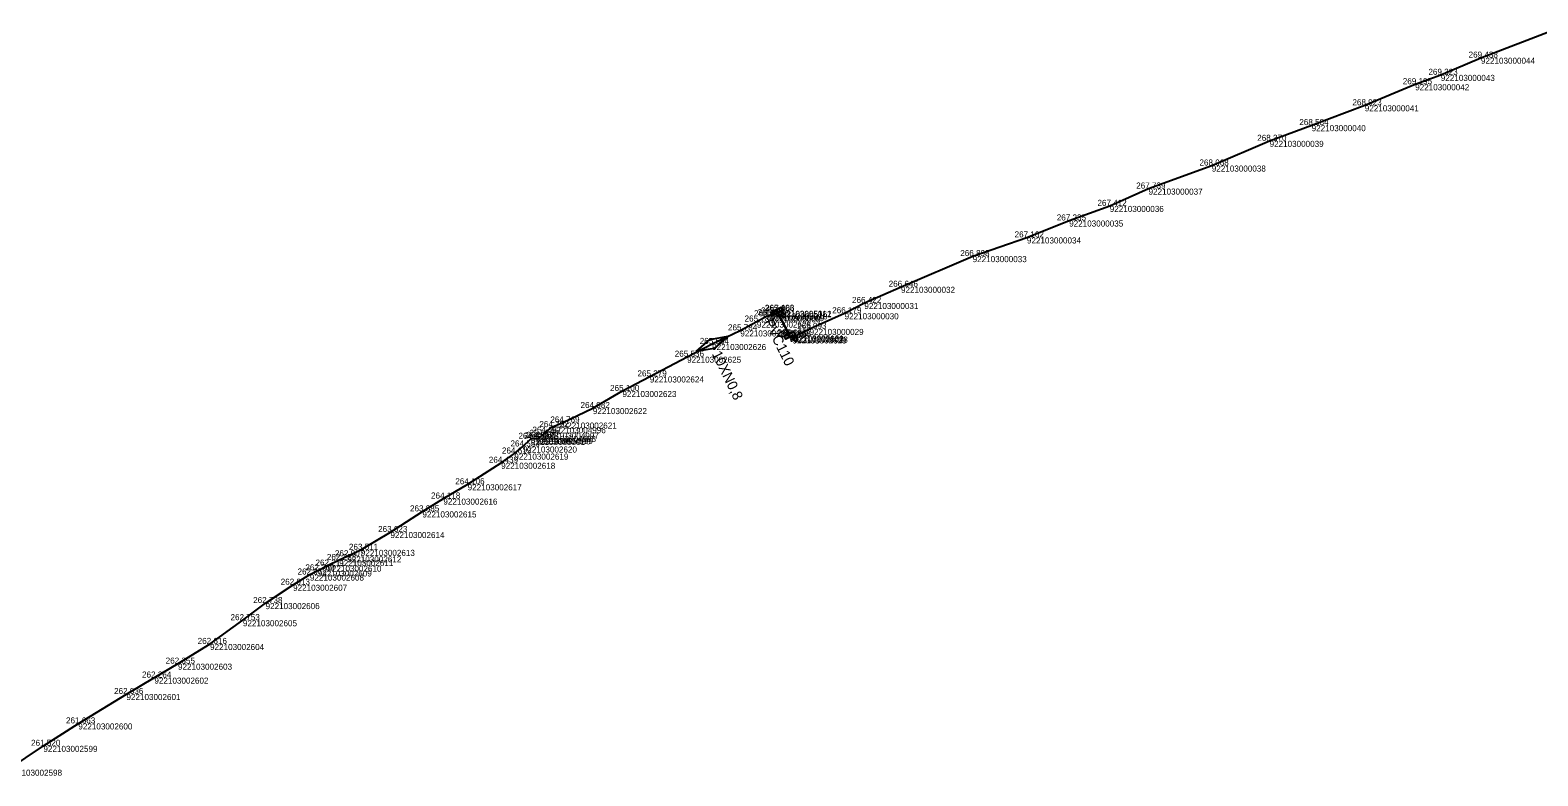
# Model space of a CAD drawing. Extents: x -771047 to -756200, y -1053876 to -1046520.
# Drawn here: x -762224.4 to -761925.6, y -1050432.5 to -1050284.9 of the extents above; entities that cross this region are included whole.
import ezdxf

# ---------------------------------------------------------------- set-up
doc = ezdxf.new("R2010")
doc.units = 0
for name, color, linetype in [('Vrstva 32', 7, 'Continuous'), ('Vrstva 33', 7, 'Continuous'), ('Vrstva 60', 7, 'Continuous'), ('Vrstva 61', 7, 'Continuous')]:
    doc.layers.add(name, color=color, linetype=linetype)

msp = doc.modelspace()

# ---------------------------------------------------------------- linework, layer by layer
at = {"layer": 'Vrstva 32'}
for points in [[(-762228.75, -1050431.27), (-762221.73, -1050426.55), (-762214.81, -1050422.11), (-762205.28, -1050416.29), (-762199.74, -1050413.04), (-762195.06, -1050410.28), (-762188.71, -1050406.38), (-762182.2, -1050401.68), (-762177.71, -1050398.29), (-762172.26, -1050394.66), (-762168.93, -1050392.64), (-762167.37, -1050391.82), (-762165.46, -1050390.88), (-762163.11, -1050389.76), (-762161.53, -1050389.03), (-762158.84, -1050387.75), (-762152.97, -1050384.22), (-762146.64, -1050380.14), (-762142.48, -1050377.6), (-762137.67, -1050374.77), (-762131.03, -1050370.51), (-762128.42, -1050368.69), (-762126.73, -1050367.29), (-762125.16, -1050365.77), (-762124.01, -1050365.69), (-762123.58, -1050365.58), (-762122.96, -1050365.19), (-762122.39, -1050364.57), (-762121.02, -1050363.46), (-762118.84, -1050362.55), (-762112.86, -1050359.68), (-762107.01, -1050356.3), (-762101.58, -1050353.42), (-762094.19, -1050349.51), (-762089.24, -1050346.99), (-762083.65, -1050344.31), (-762080.36, -1050342.56), (-762078.48, -1050341.51), (-762077.75, -1050341.27), (-762077.09, -1050340.94), (-762076.32, -1050340.42), (-762073.88, -1050345.37), (-762073.3, -1050345.7), (-762073.06, -1050345.53), (-762069.93, -1050344.01), (-762062.99, -1050340.91), (-762059.07, -1050338.88), (-762051.81, -1050335.67), (-762037.61, -1050329.6), (-762026.86, -1050325.9), (-762018.49, -1050322.55), (-762010.45, -1050319.66), (-762002.76, -1050316.23), (-761990.23, -1050311.67), (-761978.78, -1050306.78), (-761970.44, -1050303.67), (-761959.92, -1050299.74), (-761949.93, -1050295.57), (-761944.86, -1050293.72), (-761936.9, -1050290.32), (-761922.65, -1050284.88)], [(-762092.4, -1050348.51), (-762089.68, -1050346.09), (-762086.09, -1050345.48), (-762088.81, -1050347.9), (-762092.4, -1050348.51)]]:
    msp.add_lwpolyline(points, dxfattribs=at)
at = {"layer": 'Vrstva 33'}
for points in [[(-762075.53, -1050339.71), (-762075.21, -1050340.37), (-762077.01, -1050341.27), (-762077.34, -1050340.6)], [(-762073.14, -1050344.5), (-762072.81, -1050345.17), (-762074.61, -1050346.06), (-762074.94, -1050345.39)]]:
    msp.add_lwpolyline(points, close=True, dxfattribs=at)
for points in [[(-762073.88, -1050345.37), (-762076.32, -1050340.42)], [(-762076.09, -1050341.4), (-762074.97, -1050340.84)], [(-762075.29, -1050341.58), (-762075.52, -1050341.12)], [(-762074.74, -1050341.31), (-762074.72, -1050341.47), (-762074.85, -1050341.66), (-762074.95, -1050341.71), (-762075.18, -1050341.7), (-762075.29, -1050341.58)], [(-762074.97, -1050340.84), (-762074.74, -1050341.31)], [(-762073.7, -1050346.19), (-762072.57, -1050345.63)], [(-762072.9, -1050346.37), (-762073.13, -1050345.91)], [(-762072.34, -1050346.1), (-762072.32, -1050346.26), (-762072.45, -1050346.45), (-762072.55, -1050346.5), (-762072.79, -1050346.5), (-762072.9, -1050346.37)], [(-762072.57, -1050345.63), (-762072.34, -1050346.1)]]:
    msp.add_lwpolyline(points, dxfattribs=at)
at = {"layer": 'Vrstva 60'}
for p, q in [((-761936.9, -1050290.32), (-761936.9, -1050290.32)), ((-761944.86, -1050293.72), (-761944.86, -1050293.72)), ((-761949.93, -1050295.57), (-761949.93, -1050295.57)), ((-761959.92, -1050299.74), (-761959.92, -1050299.74)), ((-761970.44, -1050303.67), (-761970.44, -1050303.67)), ((-761978.78, -1050306.78), (-761978.78, -1050306.78)), ((-761990.23, -1050311.67), (-761990.23, -1050311.67)), ((-762002.76, -1050316.23), (-762002.76, -1050316.23)), ((-762010.45, -1050319.66), (-762010.45, -1050319.66)), ((-762018.49, -1050322.55), (-762018.49, -1050322.55)), ((-762026.86, -1050325.9), (-762026.86, -1050325.9)), ((-762037.61, -1050329.6), (-762037.61, -1050329.6)), ((-762051.81, -1050335.67), (-762051.81, -1050335.67)), ((-762059.07, -1050338.88), (-762059.07, -1050338.88)), ((-762078.48, -1050341.51), (-762078.48, -1050341.51)), ((-762077.75, -1050341.27), (-762077.75, -1050341.27)), ((-762077.09, -1050340.94), (-762077.09, -1050340.94)), ((-762076.32, -1050340.42), (-762076.32, -1050340.42)), ((-762076.27, -1050340.49), (-762076.27, -1050340.49)), ((-762062.99, -1050340.91), (-762062.99, -1050340.91)), ((-762083.65, -1050344.31), (-762083.65, -1050344.31)), ((-762080.36, -1050342.56), (-762080.36, -1050342.56)), ((-762069.93, -1050344.01), (-762069.93, -1050344.01)), ((-762089.24, -1050346.99), (-762089.24, -1050346.99)), ((-762073.88, -1050345.28), (-762073.88, -1050345.28)), ((-762073.88, -1050345.37), (-762073.88, -1050345.37)), ((-762073.3, -1050345.7), (-762073.3, -1050345.7)), ((-762073.06, -1050345.53), (-762073.06, -1050345.53)), ((-762094.19, -1050349.51), (-762094.19, -1050349.51)), ((-762101.58, -1050353.42), (-762101.58, -1050353.42)), ((-762107.01, -1050356.3), (-762107.01, -1050356.3)), ((-762112.86, -1050359.68), (-762112.86, -1050359.68)), ((-762118.84, -1050362.55), (-762118.84, -1050362.55)), ((-762125.16, -1050365.77), (-762125.16, -1050365.77)), ((-762124.01, -1050365.69), (-762124.01, -1050365.69)), ((-762123.58, -1050365.58), (-762123.58, -1050365.58)), ((-762122.96, -1050365.19), (-762122.96, -1050365.19)), ((-762122.39, -1050364.57), (-762122.39, -1050364.57)), ((-762121.02, -1050363.46), (-762121.02, -1050363.46)), ((-762128.42, -1050368.69), (-762128.42, -1050368.69)), ((-762126.73, -1050367.29), (-762126.73, -1050367.29)), ((-762131.03, -1050370.51), (-762131.03, -1050370.51)), ((-762137.67, -1050374.77), (-762137.67, -1050374.77)), ((-762142.48, -1050377.6), (-762142.48, -1050377.6)), ((-762146.64, -1050380.14), (-762146.64, -1050380.14)), ((-762152.97, -1050384.22), (-762152.97, -1050384.22)), ((-762163.11, -1050389.76), (-762163.11, -1050389.76)), ((-762161.53, -1050389.03), (-762161.53, -1050389.03)), ((-762158.84, -1050387.75), (-762158.84, -1050387.75)), ((-762168.93, -1050392.64), (-762168.93, -1050392.64)), ((-762167.37, -1050391.82), (-762167.37, -1050391.82)), ((-762165.46, -1050390.88), (-762165.46, -1050390.88)), ((-762172.26, -1050394.66), (-762172.26, -1050394.66)), ((-762177.71, -1050398.29), (-762177.71, -1050398.29)), ((-762182.2, -1050401.68), (-762182.2, -1050401.68)), ((-762188.71, -1050406.38), (-762188.71, -1050406.38)), ((-762195.06, -1050410.28), (-762195.06, -1050410.28)), ((-762199.74, -1050413.04), (-762199.74, -1050413.04)), ((-762205.28, -1050416.29), (-762205.28, -1050416.29)), ((-762214.81, -1050422.11), (-762214.81, -1050422.11)), ((-762221.73, -1050426.55), (-762221.73, -1050426.55))]:
    msp.add_line(p, q, dxfattribs=at)

# ---------------------------------------------------------------- texts
at = {"layer": 'Vrstva 32'}
msp.add_text('10XN0,8', height=2, rotation=295.6764, dxfattribs=at).set_placement((-762089.33, -1050348.93))
at = {"layer": 'Vrstva 33'}
msp.add_text('PVC110', height=2, rotation=296.2724, dxfattribs=at).set_placement((-762079.03, -1050342.63))
at = {"layer": 'Vrstva 60'}
for s, p in [('922103000044', (-761936.9, -1050291.52)), ('922103000043', (-761944.86, -1050294.92)), ('922103000042', (-761949.93, -1050296.77)), ('922103000041', (-761959.92, -1050300.94)), ('922103000040', (-761970.44, -1050304.87)), ('922103000039', (-761978.78, -1050307.98)), ('922103000038', (-761990.23, -1050312.87)), ('922103000037', (-762002.76, -1050317.43)), ('922103000036', (-762010.45, -1050320.86)), ('922103000035', (-762018.49, -1050323.75)), ('922103000034', (-762026.86, -1050327.1)), ('922103000033', (-762037.61, -1050330.8)), ('922103000032', (-762051.81, -1050336.87)), ('922103000031', (-762059.07, -1050340.08)), ('922103005008', (-762078.48, -1050342.71)), ('922103005009', (-762077.75, -1050342.47)), ('922103005010', (-762077.09, -1050342.14)), ('922103005011', (-762076.32, -1050341.62)), ('922103005162', (-762076.27, -1050341.69)), ('922103000030', (-762062.99, -1050342.11)), ('922103002627', (-762083.65, -1050345.51)), ('922103002628', (-762080.36, -1050343.76)), ('922103000029', (-762069.93, -1050345.21)), ('922103002626', (-762089.24, -1050348.19)), ('922103002630', (-762073.88, -1050346.57)), ('922103005161', (-762073.88, -1050346.48)), ('922103002629', (-762073.3, -1050346.9)), ('922103000028', (-762073.06, -1050346.73)), ('922103002625', (-762094.19, -1050350.71)), ('922103002624', (-762101.58, -1050354.62)), ('922103002623', (-762107.01, -1050357.5)), ('922103002622', (-762112.86, -1050360.88)), ('922103002621', (-762118.84, -1050363.75)), ('922103005001', (-762125.16, -1050366.97)), ('922103005000', (-762124.01, -1050366.89)), ('922103004999', (-762123.58, -1050366.78)), ('922103004998', (-762122.96, -1050366.39)), ('922103004997', (-762122.39, -1050365.77)), ('922103004996', (-762121.02, -1050364.66)), ('922103002619', (-762128.42, -1050369.89)), ('922103002620', (-762126.73, -1050368.49)), ('922103002618', (-762131.03, -1050371.71)), ('922103002617', (-762137.67, -1050375.97)), ('922103002616', (-762142.48, -1050378.8)), ('922103002615', (-762146.64, -1050381.34)), ('922103002614', (-762152.97, -1050385.42)), ('922103002611', (-762163.11, -1050390.96)), ('922103002612', (-762161.53, -1050390.23)), ('922103002613', (-762158.84, -1050388.95)), ('922103002608', (-762168.93, -1050393.84)), ('922103002609', (-762167.37, -1050393.02)), ('922103002610', (-762165.46, -1050392.08)), ('922103002607', (-762172.26, -1050395.86)), ('922103002606', (-762177.71, -1050399.49)), ('922103002605', (-762182.2, -1050402.88)), ('922103002604', (-762188.71, -1050407.58)), ('922103002603', (-762195.06, -1050411.48)), ('922103002602', (-762199.74, -1050414.24)), ('922103002601', (-762205.28, -1050417.49)), ('922103002600', (-762214.81, -1050423.31)), ('922103002599', (-762221.73, -1050427.75)), ('922103002598', (-762228.75, -1050432.47))]:
    msp.add_text(s, height=1.2, dxfattribs=at).set_placement(p)
at = {"layer": 'Vrstva 61'}
for s, p in [('269.438', (-761939.35, -1050290.32)), ('269.195', (-761952.39, -1050295.57)), ('269.323', (-761947.31, -1050293.72)), ('268.923', (-761962.37, -1050299.74)), ('268.584', (-761972.89, -1050303.67)), ('268.370', (-761981.23, -1050306.78)), ('268.068', (-761992.68, -1050311.67)), ('267.739', (-762005.21, -1050316.23)), ('267.235', (-762020.95, -1050322.55)), ('267.412', (-762012.89, -1050319.66)), ('267.162', (-762029.31, -1050325.9)), ('266.898', (-762040.07, -1050329.6)), ('266.646', (-762054.26, -1050335.67)), ('265.403', (-762078.78, -1050340.42)), ('267.066', (-762078.72, -1050340.49)), ('266.422', (-762061.52, -1050338.88)), ('265.784', (-762082.81, -1050342.56)), ('265.997', (-762080.93, -1050341.51)), ('265.929', (-762080.2, -1050341.27)), ('265.923', (-762079.54, -1050340.94)), ('266.179', (-762065.44, -1050340.91)), ('265.784', (-762086.1, -1050344.31)), ('267.163', (-762076.33, -1050345.28)), ('265.241', (-762076.24, -1050345.37)), ('265.824', (-762075.75, -1050345.7)), ('265.868', (-762075.51, -1050345.53)), ('265.993', (-762072.38, -1050344.01)), ('265.564', (-762091.69, -1050346.99)), ('265.536', (-762096.64, -1050349.51)), ('265.279', (-762104.03, -1050353.42)), ('265.100', (-762109.46, -1050356.3)), ('264.982', (-762115.31, -1050359.68)), ('264.722', (-762123.47, -1050363.46)), ('264.769', (-762121.3, -1050362.55)), ('264.553', (-762129.19, -1050367.29)), ('264.810', (-762127.61, -1050365.77)), ('264.587', (-762126.46, -1050365.69)), ('264.653', (-762126.03, -1050365.58)), ('264.700', (-762125.41, -1050365.19)), ('264.667', (-762124.84, -1050364.57)), ('264.619', (-762130.88, -1050368.69)), ('264.439', (-762133.48, -1050370.51)), ('264.106', (-762140.12, -1050374.77)), ('264.118', (-762144.93, -1050377.6)), ('263.885', (-762149.1, -1050380.14)), ('263.623', (-762155.42, -1050384.22)), ('263.511', (-762161.2, -1050387.75)), ('262.211', (-762167.82, -1050390.88)), ('262.223', (-762165.57, -1050389.76)), ('262.907', (-762163.98, -1050389.03)), ('262.972', (-762171.38, -1050392.64)), ('262.769', (-762169.83, -1050391.82)), ('262.913', (-762174.72, -1050394.66)), ('262.738', (-762180.17, -1050398.29)), ('262.753', (-762184.66, -1050401.68)), ('262.616', (-762191.17, -1050406.38)), ('262.355', (-762197.51, -1050410.28)), ('262.264', (-762202.19, -1050413.04)), ('262.036', (-762207.73, -1050416.29)), ('261.663', (-762217.26, -1050422.11)), ('261.520', (-762224.18, -1050426.55))]:
    msp.add_text(s, height=1.2, dxfattribs=at).set_placement(p)

doc.saveas('drawing.dxf')
